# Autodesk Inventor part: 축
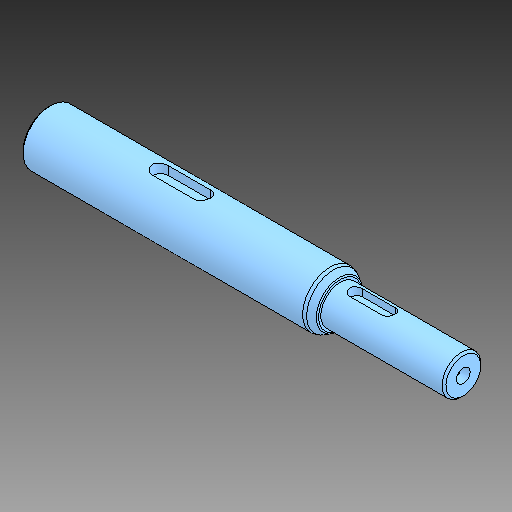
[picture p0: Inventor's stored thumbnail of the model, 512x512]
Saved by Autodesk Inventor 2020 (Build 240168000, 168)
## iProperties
Created: 2025-03
Part Number: 축
Material: 강철, 탄소
Document SubType Name: Modeling
Designer: CA01
Density: 7.85 g/cm^3
Appearance: 기본값
Author: jhkim
Sending System: Autodesk Inventor 2025
Preprocessor: ST-DEVELOPER v20
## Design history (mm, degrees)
feature "솔리드1"
node "솔리드2"
